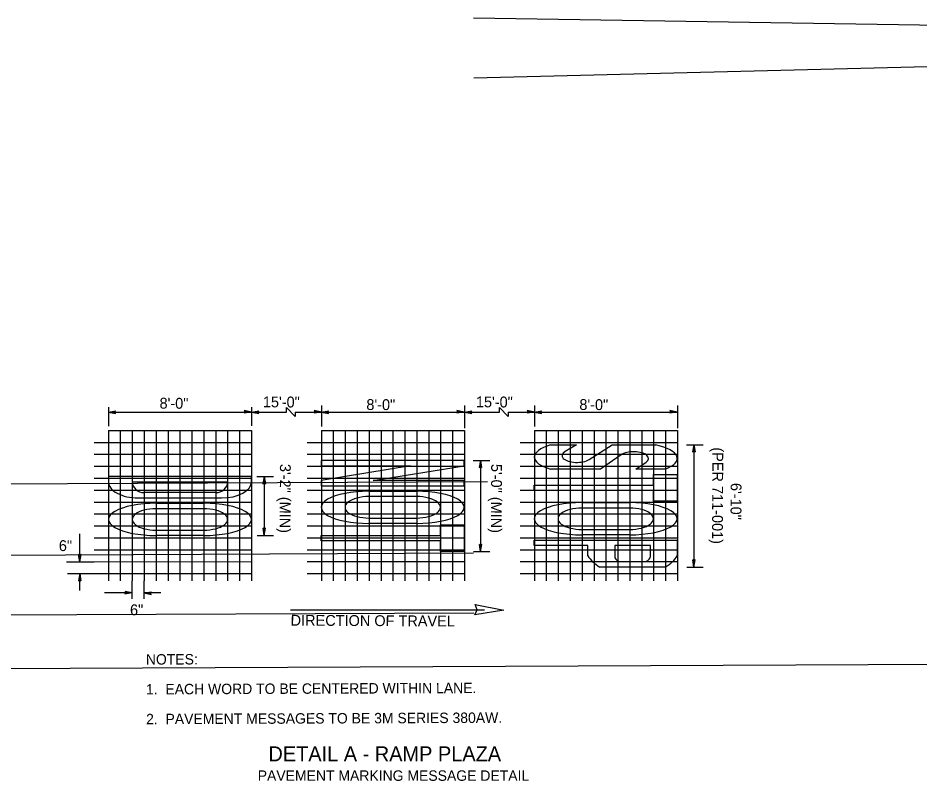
# Model space of a CAD drawing. Extents: x 583689 to 590775, y 1496016 to 1497365.
# Drawn here: x 587293 to 587898, y 1496787 to 1497298 of the extents above; entities that cross this region are included whole.
import ezdxf

# ---------------------------------------------------------------- set-up
doc = ezdxf.new("R2010")
doc.units = 0
for name, color, linetype in [('20', 7, 'Continuous'), ('21', 7, 'Continuous'), ('32', 7, 'Continuous'), ('5', 7, 'Continuous'), ('PavtMessage', 7, 'Continuous'), ('TextNotes', 7, 'Continuous')]:
    doc.layers.add(name, color=color, linetype=linetype)

msp = doc.modelspace()

# ---------------------------------------------------------------- linework, layer by layer
at = {"layer": '20'}
for p, q in [((587599.82, 1496904.89), (587619.12, 1496901.14)), ((587601.24, 1496901.44), (587599.82, 1496904.89)), ((587599.7, 1496898.06), (587601.24, 1496901.44)), ((587619.12, 1496901.14), (587599.7, 1496898.06))]:
    msp.add_line(p, q, dxfattribs=at)
at = {"layer": '21'}
for p, q in [((587353.86, 1497037.2), (587353.86, 1497024.45)), ((587449.86, 1497034.01), (587445.03, 1497034.95)), ((587445.03, 1497034.95), (587445.39, 1497034.09)), ((587449.86, 1497037.2), (587449.86, 1497024.75)), ((587473.28, 1497034.01), (587473.27, 1497036.99)), ((587473.27, 1497036.99), (587479.04, 1497031.02)), ((587496.7, 1497034.01), (587491.87, 1497034.95)), ((587491.87, 1497034.95), (587492.23, 1497034.09)), ((587496.7, 1497038.33), (587496.69, 1497024.31)), ((587592.45, 1497034.01), (587587.62, 1497034.95)), ((587587.62, 1497034.95), (587587.97, 1497034.09)), ((587592.7, 1497038.34), (587592.7, 1497023.26)), ((587592.7, 1497035.72), (587592.7, 1497023.26)), ((587616.12, 1497034.01), (587616.11, 1497036.99)), ((587616.11, 1497036.99), (587621.88, 1497031.02)), ((587639.53, 1497034.01), (587634.71, 1497034.95)), ((587634.71, 1497034.95), (587635.06, 1497034.09)), ((587639.53, 1497038.33), (587639.53, 1497024.31)), ((587735.28, 1497034.01), (587730.46, 1497034.95)), ((587730.46, 1497034.95), (587730.81, 1497034.09)), ((587735.53, 1497038.34), (587735.53, 1497023.26)), ((587735.53, 1497035.72), (587735.53, 1497023.26)), ((587353.86, 1497034.01), (587358.71, 1497034.78)), ((587353.86, 1497034.01), (587358.51, 1497034.34)), ((587353.86, 1497034.01), (587449.86, 1497034.01)), ((587353.86, 1497034.01), (587358.68, 1497033.07)), ((587353.86, 1497034.01), (587358.5, 1497033.52)), ((587358.33, 1497033.93), (587358.71, 1497034.78)), ((587358.68, 1497033.07), (587358.33, 1497033.93)), ((587445.39, 1497034.09), (587445, 1497033.24)), ((587449.86, 1497034.01), (587445, 1497033.24)), ((587449.86, 1497034.01), (587445.21, 1497033.68)), ((587449.86, 1497034.01), (587445.22, 1497034.49)), ((587449.86, 1497034.01), (587454.71, 1497034.78)), ((587449.86, 1497034.01), (587454.51, 1497034.33)), ((587449.86, 1497034.01), (587454.68, 1497033.07)), ((587449.86, 1497034.01), (587454.5, 1497033.52)), ((587449.86, 1497034.01), (587473.28, 1497034.01)), ((587454.33, 1497033.93), (587454.71, 1497034.78)), ((587454.68, 1497033.07), (587454.33, 1497033.93)), ((587479.04, 1497034.01), (587479.04, 1497031.02)), ((587479.04, 1497034.01), (587496.7, 1497034.01)), ((587492.23, 1497034.09), (587491.84, 1497033.24)), ((587496.7, 1497034.01), (587491.84, 1497033.24)), ((587496.7, 1497034.01), (587492.05, 1497034.49)), ((587496.7, 1497034.01), (587492.05, 1497033.69)), ((587496.7, 1497034.01), (587501.55, 1497034.78)), ((587496.7, 1497034.01), (587501.35, 1497034.34)), ((587496.7, 1497034.01), (587592.45, 1497034.01)), ((587496.7, 1497034.01), (587501.52, 1497033.07)), ((587496.7, 1497034.01), (587501.34, 1497033.53)), ((587501.17, 1497033.93), (587501.55, 1497034.78)), ((587501.52, 1497033.07), (587501.17, 1497033.93)), ((587587.97, 1497034.09), (587587.59, 1497033.24)), ((587592.45, 1497034.01), (587587.59, 1497033.24)), ((587592.45, 1497034.01), (587587.79, 1497033.68)), ((587592.45, 1497034.01), (587587.8, 1497034.49)), ((587592.7, 1497034.01), (587597.55, 1497034.78)), ((587592.7, 1497034.01), (587597.34, 1497034.33)), ((587592.7, 1497034.01), (587616.12, 1497034.01)), ((587592.7, 1497034.01), (587597.52, 1497033.07)), ((587592.7, 1497034.01), (587597.34, 1497033.52)), ((587597.17, 1497033.93), (587597.55, 1497034.78)), ((587597.52, 1497033.07), (587597.17, 1497033.93)), ((587621.88, 1497034.01), (587621.88, 1497031.02)), ((587621.88, 1497034.01), (587639.53, 1497034.01)), ((587635.06, 1497034.09), (587634.68, 1497033.24)), ((587639.53, 1497034.01), (587634.68, 1497033.24)), ((587639.53, 1497034.01), (587634.88, 1497033.69)), ((587639.53, 1497034.01), (587634.89, 1497034.49)), ((587639.53, 1497034.01), (587644.39, 1497034.78)), ((587639.53, 1497034.01), (587644.19, 1497034.34)), ((587639.53, 1497034.01), (587735.28, 1497034.01)), ((587639.53, 1497034.01), (587644.36, 1497033.07)), ((587639.53, 1497034.01), (587644.18, 1497033.53)), ((587644.01, 1497033.93), (587644.39, 1497034.78)), ((587644.36, 1497033.07), (587644.01, 1497033.93)), ((587730.81, 1497034.09), (587730.43, 1497033.24)), ((587735.28, 1497034.01), (587730.43, 1497033.24)), ((587735.28, 1497034.01), (587730.63, 1497033.68)), ((587735.28, 1497034.01), (587730.64, 1497034.49)), ((587353.86, 1497021.66), (587449.86, 1497021.67)), ((587353.86, 1497021.67), (587353.86, 1496920.87)), ((587361.86, 1497021.67), (587361.86, 1496920.87)), ((587369.86, 1497021.67), (587369.86, 1496920.87)), ((587377.86, 1497021.67), (587377.86, 1496920.87)), ((587385.86, 1497021.67), (587385.86, 1496920.87)), ((587393.86, 1497021.67), (587393.86, 1496920.87)), ((587401.86, 1497021.67), (587401.86, 1496920.87)), ((587409.86, 1497021.67), (587409.86, 1496920.87)), ((587417.86, 1497021.67), (587417.86, 1496920.87)), ((587425.86, 1497021.67), (587425.86, 1496920.87)), ((587433.86, 1497021.67), (587433.86, 1496920.87)), ((587441.86, 1497021.67), (587441.86, 1496920.87)), ((587449.86, 1497021.67), (587449.86, 1496920.87)), ((587496.7, 1497021.67), (587592.7, 1497021.67)), ((587496.7, 1497021.67), (587496.7, 1496920.87)), ((587504.7, 1497021.67), (587504.7, 1496920.87)), ((587512.7, 1497021.67), (587512.7, 1496920.87)), ((587520.7, 1497021.67), (587520.7, 1496920.87)), ((587528.7, 1497021.67), (587528.7, 1496920.87)), ((587536.7, 1497021.67), (587536.7, 1496920.87)), ((587544.7, 1497021.67), (587544.7, 1496920.87)), ((587552.7, 1497021.67), (587552.7, 1496920.87)), ((587560.7, 1497021.67), (587560.7, 1496920.87)), ((587568.7, 1497021.67), (587568.7, 1496920.87)), ((587576.7, 1497021.67), (587576.7, 1496920.87)), ((587584.7, 1497021.67), (587584.7, 1496920.87)), ((587592.7, 1497021.67), (587592.7, 1496920.87)), ((587639.53, 1497021.67), (587735.53, 1497021.67)), ((587639.53, 1497021.67), (587639.53, 1496920.87)), ((587647.53, 1497021.67), (587647.53, 1496920.87)), ((587655.53, 1497021.67), (587655.53, 1496920.87)), ((587663.53, 1497021.67), (587663.53, 1496920.87)), ((587671.53, 1497021.67), (587671.53, 1496920.87)), ((587679.53, 1497021.67), (587679.53, 1496920.87)), ((587687.53, 1497021.67), (587687.53, 1496920.87)), ((587695.53, 1497021.67), (587695.53, 1496920.87)), ((587703.53, 1497021.67), (587703.53, 1496920.87)), ((587711.53, 1497021.67), (587711.53, 1496920.87)), ((587719.53, 1497021.67), (587719.53, 1496920.87)), ((587727.53, 1497021.67), (587727.53, 1496920.87)), ((587735.53, 1497021.67), (587735.53, 1496920.87)), ((587344.26, 1497013.66), (587449.86, 1497013.67)), ((587487.1, 1497013.67), (587592.7, 1497013.67)), ((587629.94, 1497013.67), (587735.53, 1497013.67)), ((587741.52, 1497012.07), (587752.73, 1497012.07)), ((587746.5, 1497012.07), (587745.56, 1497007.24)), ((587746.5, 1497012.07), (587746.02, 1497007.43)), ((587746.5, 1497012.07), (587746.5, 1496930.07)), ((587746.5, 1497012.07), (587747.27, 1497007.21)), ((587746.5, 1497012.07), (587746.83, 1497007.42)), ((587344.26, 1497005.66), (587449.86, 1497005.67)), ((587487.1, 1497005.67), (587592.7, 1497005.67)), ((587629.94, 1497005.67), (587735.53, 1497005.67)), ((587745.56, 1497007.24), (587746.42, 1497007.6)), ((587746.42, 1497007.6), (587747.27, 1497007.21)), ((587598.42, 1497001.6), (587609.63, 1497001.6)), ((587603.41, 1497001.61), (587602.47, 1496996.78)), ((587603.41, 1497001.61), (587602.92, 1496996.97)), ((587603.41, 1497001.61), (587604.18, 1496996.75)), ((587603.41, 1497001.61), (587603.73, 1496996.96)), ((587603.41, 1497001.61), (587603.41, 1496940.38)), ((587344.26, 1496997.66), (587449.86, 1496997.67)), ((587487.1, 1496997.67), (587592.7, 1496997.67)), ((587602.47, 1496996.78), (587603.33, 1496997.14)), ((587603.33, 1496997.14), (587604.18, 1496996.75)), ((587629.94, 1496997.67), (587735.53, 1496997.67)), ((587344.26, 1496989.66), (587449.86, 1496989.67)), ((587453.38, 1496990.8), (587464.59, 1496990.8)), ((587458.36, 1496990.78), (587457.43, 1496985.96)), ((587458.36, 1496990.78), (587457.88, 1496986.14)), ((587458.36, 1496990.78), (587459.13, 1496985.93)), ((587458.36, 1496990.78), (587458.69, 1496986.13)), ((587458.36, 1496990.78), (587458.36, 1496951.21)), ((587487.1, 1496989.67), (587592.7, 1496989.67)), ((587629.94, 1496989.67), (587735.53, 1496989.67)), ((587344.26, 1496981.66), (587449.86, 1496981.67)), ((587457.43, 1496985.96), (587458.29, 1496986.31)), ((587458.29, 1496986.31), (587459.13, 1496985.93)), ((587487.1, 1496981.67), (587592.7, 1496981.67)), ((587629.94, 1496981.67), (587735.53, 1496981.67)), ((587344.26, 1496973.66), (587449.86, 1496973.67)), ((587487.1, 1496973.67), (587592.7, 1496973.67)), ((587629.94, 1496973.67), (587735.53, 1496973.67)), ((587344.26, 1496965.66), (587449.86, 1496965.67)), ((587487.1, 1496965.67), (587592.7, 1496965.67)), ((587629.94, 1496965.67), (587735.53, 1496965.67)), ((587344.26, 1496957.66), (587449.86, 1496957.67)), ((587487.1, 1496957.67), (587592.7, 1496957.67)), ((587629.94, 1496957.67), (587735.54, 1496957.67)), ((587334.68, 1496933.66), (587334.68, 1496952.31)), ((587453.68, 1496951.2), (587464.58, 1496951.2)), ((587458.36, 1496951.21), (587457.59, 1496956.07)), ((587458.44, 1496955.68), (587457.59, 1496956.07)), ((587458.36, 1496951.21), (587458.04, 1496955.86)), ((587458.36, 1496951.21), (587459.3, 1496956.04)), ((587458.36, 1496951.21), (587458.85, 1496955.85)), ((587459.3, 1496956.04), (587458.44, 1496955.68)), ((587344.26, 1496949.66), (587449.86, 1496949.67)), ((587487.1, 1496949.67), (587592.7, 1496949.67)), ((587603.41, 1496940.38), (587602.64, 1496945.24)), ((587603.48, 1496944.85), (587602.64, 1496945.24)), ((587603.41, 1496940.38), (587603.08, 1496945.03)), ((587603.41, 1496940.38), (587604.34, 1496945.21)), ((587603.41, 1496940.38), (587603.89, 1496945.02)), ((587604.34, 1496945.21), (587603.48, 1496944.85)), ((587629.94, 1496949.67), (587735.54, 1496949.67)), ((587334.68, 1496933.66), (587333.91, 1496938.52)), ((587334.76, 1496938.13), (587333.91, 1496938.52)), ((587334.68, 1496933.66), (587334.35, 1496938.31)), ((587334.68, 1496933.66), (587335.61, 1496938.49)), ((587334.68, 1496933.66), (587335.16, 1496938.3)), ((587335.61, 1496938.49), (587334.76, 1496938.13)), ((587344.26, 1496941.66), (587449.86, 1496941.67)), ((587487.1, 1496941.67), (587592.7, 1496941.67)), ((587598.73, 1496940.38), (587609.63, 1496940.38)), ((587629.94, 1496941.67), (587735.54, 1496941.67)), ((587325.72, 1496933.66), (587344.26, 1496933.66)), ((587344.26, 1496933.66), (587449.86, 1496933.67)), ((587487.1, 1496933.67), (587592.7, 1496933.67)), ((587629.94, 1496933.67), (587735.54, 1496933.67)), ((587746.5, 1496930.07), (587745.73, 1496934.93)), ((587746.58, 1496934.54), (587745.73, 1496934.93)), ((587746.5, 1496930.07), (587746.17, 1496934.72)), ((587746.5, 1496930.07), (587747.44, 1496934.9)), ((587746.5, 1496930.07), (587746.99, 1496934.71)), ((587747.44, 1496934.9), (587746.58, 1496934.54)), ((587741.82, 1496930.06), (587752.73, 1496930.06)), ((587326.47, 1496925.62), (587344.26, 1496925.62)), ((587334.68, 1496925.62), (587333.74, 1496920.79)), ((587333.74, 1496920.79), (587334.6, 1496921.15)), ((587334.68, 1496925.62), (587334.19, 1496920.98)), ((587334.6, 1496921.15), (587335.45, 1496920.76)), ((587334.68, 1496914.43), (587334.68, 1496925.62)), ((587334.68, 1496925.62), (587335.45, 1496920.76)), ((587334.68, 1496925.62), (587335, 1496920.97)), ((587344.26, 1496925.66), (587449.86, 1496925.67)), ((587369.86, 1496908.82), (587369.86, 1496920.87)), ((587377.85, 1496908.82), (587377.86, 1496920.87)), ((587487.1, 1496925.67), (587592.7, 1496925.67)), ((587629.94, 1496925.67), (587735.54, 1496925.67)), ((587369.86, 1496912.66), (587351.21, 1496912.66)), ((587365.39, 1496912.74), (587365, 1496911.89)), ((587369.86, 1496912.66), (587365, 1496911.89)), ((587369.86, 1496912.66), (587365.03, 1496913.6)), ((587365.03, 1496913.6), (587365.39, 1496912.74)), ((587369.86, 1496912.66), (587365.21, 1496912.33)), ((587369.86, 1496912.66), (587365.22, 1496913.15)), ((587377.85, 1496912.66), (587382.71, 1496913.43)), ((587377.85, 1496912.66), (587382.5, 1496912.98)), ((587389.04, 1496912.66), (587377.85, 1496912.66)), ((587377.85, 1496912.66), (587382.68, 1496911.72)), ((587377.85, 1496912.66), (587382.49, 1496912.18)), ((587382.32, 1496912.59), (587382.71, 1496913.43)), ((587382.68, 1496911.72), (587382.32, 1496912.59)), ((587476.07, 1496901.29), (587606.06, 1496901.3))]:
    msp.add_line(p, q, dxfattribs=at)
at = {"layer": '5'}
for p, q in [((588098.73, 1497290.4), (587598.69, 1497298.22)), ((587598.86, 1497258.23), (588098.81, 1497270.47)), ((585969.09, 1496980.1), (587608.17, 1496987.35)), ((587598.69, 1496939.31), (583688.73, 1496922.03)), ((583688.9, 1496882.03), (587598.86, 1496899.31)), ((588199.06, 1496865.96), (586110.22, 1496856.73))]:
    msp.add_line(p, q, dxfattribs=at)
at = {"layer": 'PavtMessage'}
for p, q in [((587650.3, 1497011.92), (587667.76, 1497011.92)), ((587667.76, 1497011.92), (587660.19, 1497007.45)), ((587676.28, 1497002.12), (587691.72, 1497011.92)), ((587691.72, 1497011.92), (587721.05, 1497011.92)), ((587697.69, 1497005.37), (587683.87, 1496995.73)), ((587592.5, 1497001.61), (587496.64, 1497001.61)), ((587496.64, 1497001.61), (587496.64, 1496998.01)), ((587592.5, 1496998.01), (587592.5, 1497001.61)), ((587707.49, 1496995.73), (587714.41, 1497000.45)), ((587496.64, 1496998.01), (587556.55, 1496998.01)), ((587556.55, 1496998.01), (587496.64, 1496988.11)), ((587531.4, 1496988.11), (587592.5, 1496998.01)), ((587683.87, 1496995.73), (587650.3, 1496995.73)), ((587727.2, 1496995.73), (587707.49, 1496995.73)), ((587449.79, 1496990.78), (587353.93, 1496990.78)), ((587353.93, 1496990.78), (587353.93, 1496987.18)), ((587369.92, 1496987.18), (587433.83, 1496987.18)), ((587449.79, 1496987.18), (587449.79, 1496990.78)), ((587496.64, 1496988.11), (587496.64, 1496984.52)), ((587592.5, 1496988.11), (587531.4, 1496988.11)), ((587592.5, 1496984.52), (587592.5, 1496988.11)), ((587719.36, 1496992.13), (587735.34, 1496992.13)), ((587719.36, 1496984.94), (587719.36, 1496992.13)), ((587735.34, 1496992.13), (587735.34, 1496974.14)), ((587496.64, 1496984.52), (587592.5, 1496984.52)), ((587528.59, 1496980.92), (587560.55, 1496980.92)), ((587639.48, 1496981.34), (587639.48, 1496984.94)), ((587639.48, 1496984.94), (587719.36, 1496984.94)), ((587719.36, 1496981.34), (587639.48, 1496981.34)), ((587719.36, 1496974.14), (587719.36, 1496981.34)), ((587373.9, 1496976.39), (587429.82, 1496976.39)), ((587425.82, 1496979.99), (587377.89, 1496979.99)), ((587560.55, 1496977.32), (587528.59, 1496977.32)), ((587385.88, 1496972.79), (587417.84, 1496972.79)), ((587417.84, 1496969.2), (587385.88, 1496969.2)), ((587671.43, 1496973.24), (587703.39, 1496973.24)), ((587703.39, 1496969.64), (587671.43, 1496969.64)), ((587735.34, 1496974.14), (587719.36, 1496974.14)), ((587528.59, 1496962.93), (587560.55, 1496962.93)), ((587560.55, 1496959.33), (587528.59, 1496959.33)), ((587576.53, 1496958.37), (587592.5, 1496958.37)), ((587576.53, 1496951.17), (587576.53, 1496958.37)), ((587592.5, 1496958.37), (587592.5, 1496940.38)), ((587385.88, 1496954.8), (587417.84, 1496954.8)), ((587417.84, 1496951.21), (587385.88, 1496951.21)), ((587496.64, 1496947.58), (587496.64, 1496951.17)), ((587496.64, 1496951.17), (587576.53, 1496951.17)), ((587671.43, 1496955.25), (587703.39, 1496955.25)), ((587703.39, 1496951.65), (587671.43, 1496951.65)), ((587576.53, 1496947.58), (587496.64, 1496947.58)), ((587576.53, 1496940.38), (587576.53, 1496947.58)), ((587639.48, 1496948.06), (587735.34, 1496948.06)), ((587639.48, 1496944.46), (587639.48, 1496948.06)), ((587675.43, 1496944.46), (587639.48, 1496944.46)), ((587675.43, 1496937.57), (587675.43, 1496944.46)), ((587717.37, 1496944.46), (587693.4, 1496944.46)), ((587693.4, 1496944.46), (587693.4, 1496937.26)), ((587717.37, 1496937.26), (587717.37, 1496944.46)), ((587735.34, 1496948.06), (587735.34, 1496937.57)), ((587592.5, 1496940.38), (587576.53, 1496940.38)), ((587696.45, 1496933.67), (587714.32, 1496933.67)), ((587727.32, 1496930.07), (587683.45, 1496930.07))]:
    msp.add_line(p, q, dxfattribs=at)
for centre, major_axis, ratio, start_param, end_param in [((587671.43, 1497003.82), (-31.95, 0), 0.337782, 5.435123, 7.131247), ((587703.39, 1497002.92), (31.95, 0), 0.337782, 5.553458, 7.268296), ((587668.13, 1497004.72), (9.99, 0), 0.450376, 2.490106, 5.666015), ((587706.08, 1497002.92), (9.99, 0), 0.450376, 5.699287, 8.851109), ((587373.9, 1496987.18), (19.97, 0), 0.540451, 3.141593, 4.71335), ((587377.91, 1496987.18), (7.99, 0), 0.900751, 3.141593, 4.712389), ((587425.84, 1496987.18), (7.99, 0), 0.900751, 4.712389, 6.283185), ((587429.82, 1496987.18), (19.97, 0), 0.540451, 4.71335, 6.283185), ((587528.59, 1496970.12), (31.95, 0), 0.337782, 1.570796, 4.712389), ((587560.55, 1496970.12), (31.95, 0), 0.337782, 4.712389, 7.853982), ((587528.59, 1496970.12), (15.98, 0), 0.450376, 1.570796, 4.712389), ((587560.55, 1496970.12), (15.98, 0), 0.450376, 4.712389, 7.853982), ((587385.88, 1496962), (31.95, 0), 0.337782, 1.570796, 4.712389), ((587385.88, 1496962), (15.98, 0), 0.450376, 1.570796, 4.712389), ((587417.84, 1496962), (31.95, 0), 0.337782, 4.712389, 7.853982), ((587417.84, 1496962), (15.98, 0), 0.450376, 4.712389, 7.853982), ((587671.43, 1496962.45), (31.95, 0), 0.337782, 1.570796, 4.712389), ((587671.43, 1496962.45), (15.98, 0), 0.450376, 1.570796, 4.712389), ((587703.39, 1496962.45), (31.95, 0), 0.337782, 4.712389, 7.853982), ((587703.39, 1496962.45), (15.98, 0), 0.450376, 4.712389, 7.853982), ((587705.38, 1496944.46), (31.95, 0), 0.619266, 3.497014, 3.955933), ((587705.38, 1496937.26), (11.98, 0), 0.450376, 3.141593, 3.87132), ((587705.38, 1496937.26), (11.98, 0), 0.450376, 5.553458, 6.283185), ((587705.38, 1496944.46), (31.95, 0), 0.619266, 5.468845, 5.927764)]:
    msp.add_ellipse(centre, major_axis=major_axis, ratio=ratio, start_param=start_param, end_param=end_param, dxfattribs=at)

# ---------------------------------------------------------------- texts
at = {"layer": '20'}
for s, height, rotation, p in [(' 8\'-0"', 7.267, 359.70123, (587385.47, 1497036.31)), (' 15\'-0"', 7.267, 359.70123, (587454.76, 1497037.2)), (' 8\'-0"', 7.267, 359.70123, (587524.15, 1497035.41)), (' 15\'-0"', 7.267, 359.70123, (587597.6, 1497037.2)), (' 8\'-0"', 7.267, 359.70123, (587666.98, 1497035.41)), ('(PER 711-001)', 7.2669, 269.70123, (587758.97, 1497010.35)), ('3\'-2" (MIN)', 7.2669, 269.70123, (587468.93, 1496999.23)), ('5\'-0" (MIN)', 7.2669, 269.70123, (587610.57, 1496999.23)), ('6\'-10"', 7.267, 269.70123, (587771.2, 1496986.47)), ('6"', 7.267, 359.70123, (587320.65, 1496940.8)), ('6"', 7.267, 359.70123, (587368.38, 1496897.76)), ('DIRECTION OF TRAVEL', 7.2669, 359.70123, (587476.07, 1496890.76))]:
    msp.add_text(s, height=height, rotation=rotation, dxfattribs=at).set_placement(p)
at = {"layer": '32'}
for s, height, p in [('DETAIL A - RAMP PLAZA', 10, (587461.2, 1496799.78)), ('PAVEMENT MARKING MESSAGE DETAIL', 7, (587454.02, 1496786.69))]:
    msp.add_text(s, height=height, rotation=0.00473, dxfattribs=at).set_placement(p)
at = {"layer": 'TextNotes'}
for s, p in [('NOTES:', (587379.03, 1496864.6)), ('1.  EACH WORD TO BE CENTERED WITHIN LANE.', (587379.11, 1496844.6)), ('2.  PAVEMENT MESSAGES TO BE 3M SERIES 380AW.', (587379.19, 1496824.61))]:
    msp.add_text(s, height=7, rotation=0.23586, dxfattribs=at).set_placement(p)

doc.saveas('drawing.dxf')
